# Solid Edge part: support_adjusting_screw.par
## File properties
Title: Support adjusting screw
Author: Robert a Rhodes jr
Template: Normal.par
Last saved by: Cadcim
Revision: 7
Application: Solid Edge
Material: aluminum
Accuracy: 0.99
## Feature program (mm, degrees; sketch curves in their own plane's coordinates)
sketch for "unnamed Protrusion 1" plane through (0, 0, 0) normal (0, -1, 0) x-axis (1, 0, 0)
  circle centre (0, 0) radius 38.1
extrude "unnamed Protrusion 1" add finite 584.2 along +normal
sketch for "ExtrudedCutout_1" plane through (0, -521.208, 0) normal (0, -1, 0) x-axis (1, 0, 0)
extrude "ExtrudedCutout_1" cut finite 76.2 along +normal  Plane_Distance = 62.992 mm
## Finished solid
Body 1: solid body, 5 faces, 4 edges, 0 vertices.
  Faces by surface: plane 3, cylinder 2
  Edges by curve: circle 4
Bounding box of the edges (mm): 76.200 x 584.200 x 76.200, from (-38.1, -584.2, -38.1) to (38.1, 0, 38.1).
Cylindrical faces by radius (mm): R25.4 x1, R38.1 x1
Planar faces by outward normal: +y 1, -y 2
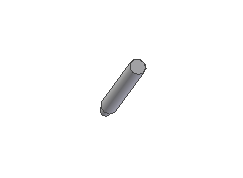
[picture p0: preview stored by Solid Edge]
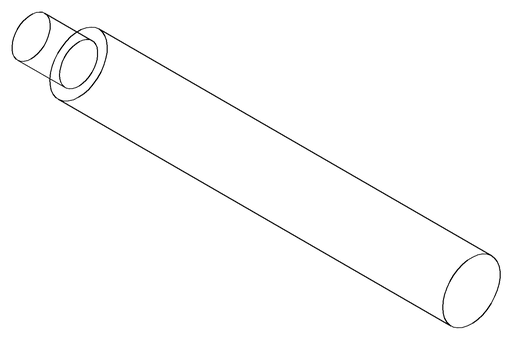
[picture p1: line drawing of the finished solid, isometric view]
